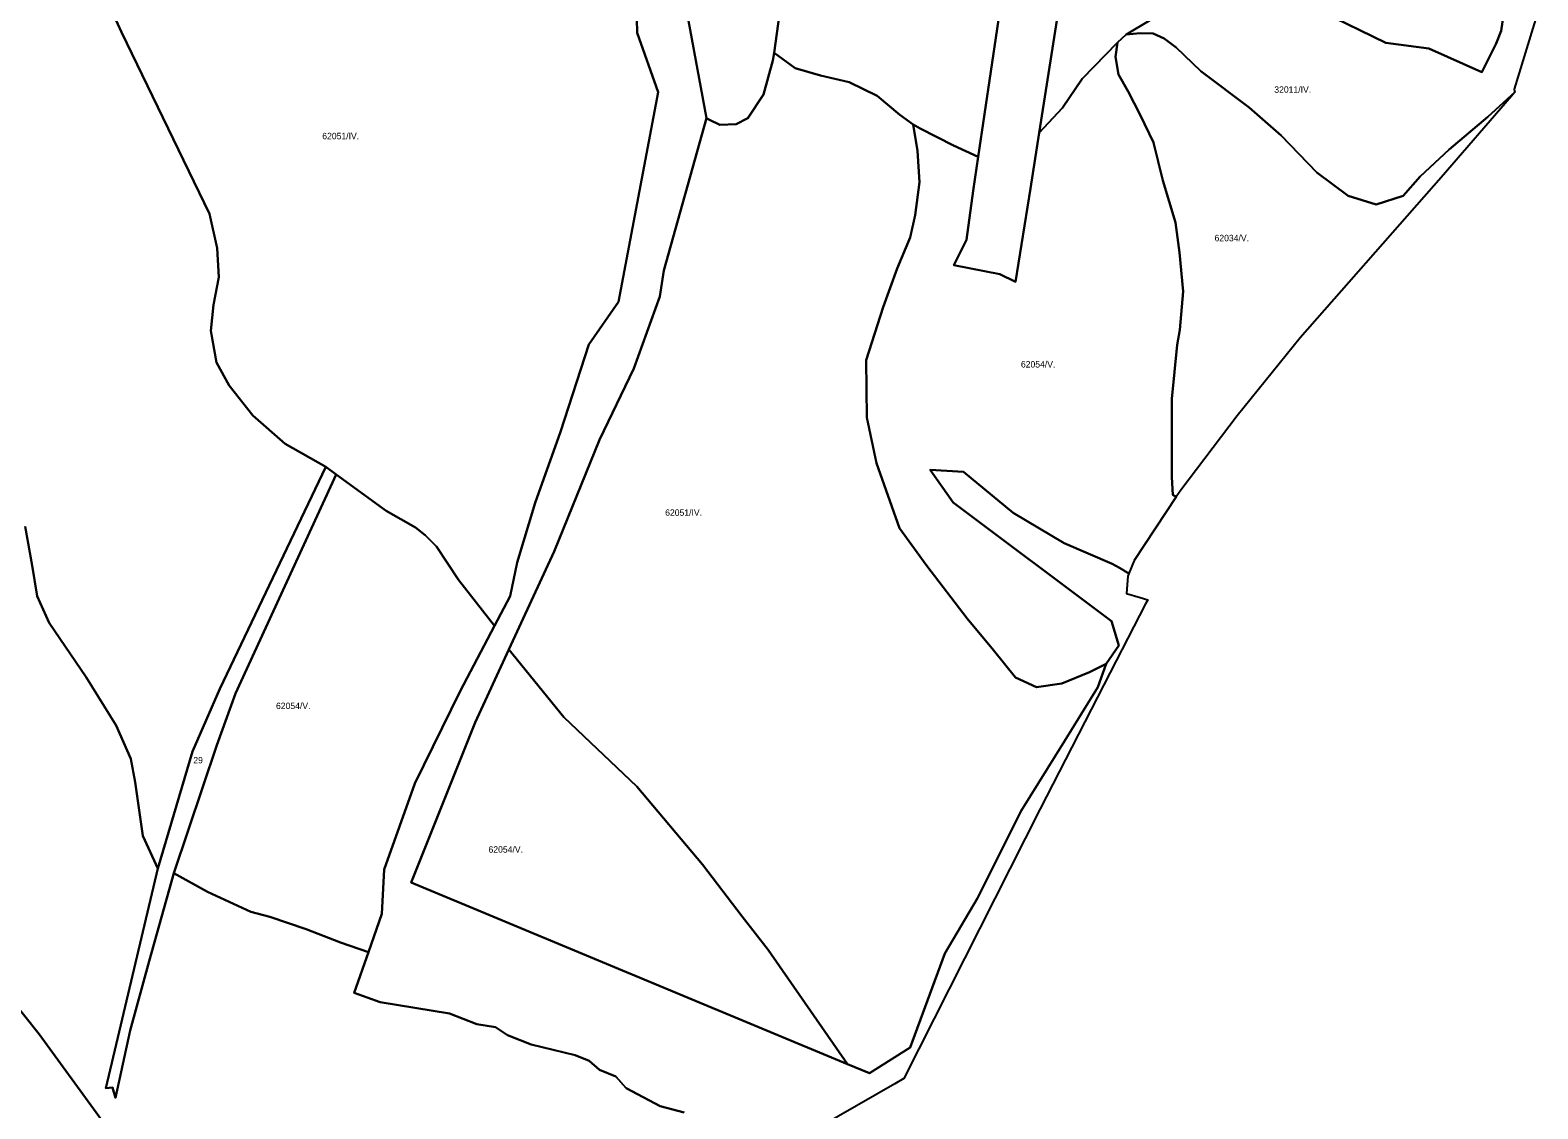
# Model space of a CAD drawing. Extents: x -521621 to -516761, y -1190184 to -1184927.
# Drawn here: x -518423 to -517486, y -1188763 to -1188092 of the extents above; entities that cross this region are included whole.
import ezdxf

# ---------------------------------------------------------------- set-up
doc = ezdxf.new("R2010")
doc.units = 0
doc.layers.add('BPEJ_s', color=7, linetype='Continuous')

msp = doc.modelspace()

# ---------------------------------------------------------------- linework, layer by layer
at = {"layer": 'BPEJ_s'}
for points in [[(-518018.47, -1188061.62), (-518012.46, -1188036.29), (-518000.06, -1188017), (-517983.54, -1188011.03), (-517972.06, -1188014.7), (-517961.5, -1188041.34), (-517957.37, -1188082.23), (-517960.81, -1188106.35), (-517961.5, -1188111.16), (-517967.47, -1188132.29), (-517977.11, -1188146.99), (-517984.45, -1188150.67), (-517994.55, -1188151.13), (-518000.98, -1188147.91), (-518002.81, -1188146.9)], [(-517795.95, -1188155.97), (-517778.93, -1188047.85), (-517760.33, -1188054.17), (-517726.82, -1188062.71), (-517690.18, -1188069.86), (-517726.97, -1188086.09), (-517741.81, -1188094.89), (-517747.31, -1188099.84), (-517769.3, -1188122.39), (-517781.39, -1188140.55)], [(-517874.36, -1188150.84), (-517869.9, -1188153.42), (-517849.15, -1188163.89), (-517833.89, -1188171.06), (-517837.01, -1188192.21), (-517841.13, -1188222.59), (-517849, -1188238.34), (-517820.52, -1188243.96), (-517810.78, -1188248.83), (-517801.42, -1188190.71), (-517795.95, -1188155.97), (-517781.39, -1188140.55), (-517769.3, -1188122.39), (-517747.31, -1188099.84), (-517748.63, -1188108.79), (-517746.75, -1188119.77), (-517740.74, -1188130.42), (-517733.2, -1188144.83), (-517724.96, -1188162.17), (-517719.13, -1188185.68), (-517711.24, -1188211.77), (-517708.67, -1188230.48), (-517706.44, -1188254.68), (-517708.5, -1188278.71), (-517710.21, -1188287.98), (-517713.53, -1188321.61), (-517713.53, -1188370.25), (-517712.98, -1188381.18), (-517710.77, -1188382.58), (-517736.9, -1188422.17), (-517740.28, -1188430.26), (-517746.03, -1188426.56), (-517750.63, -1188424.26), (-517780.51, -1188411.31), (-517812.07, -1188392.51), (-517843.13, -1188366.94), (-517863.67, -1188365.69), (-517849.4, -1188385.99), (-517750.96, -1188459.75), (-517746.36, -1188474.86), (-517754.24, -1188486.36), (-517764.66, -1188491.5), (-517781.81, -1188498.69), (-517797.65, -1188500.87), (-517810.75, -1188494.86), (-517824.41, -1188477.92), (-517840.8, -1188458.24), (-517865.92, -1188425.45), (-517882.85, -1188401.95), (-517897.05, -1188361.51), (-517903.06, -1188333.09), (-517903.61, -1188297.56), (-517892.89, -1188264.55), (-517884.31, -1188240.52), (-517876.25, -1188221.21), (-517872.99, -1188207.31), (-517870.42, -1188186.71), (-517871.62, -1188167.32)], [(-517747.31, -1188099.84), (-517741.81, -1188094.89), (-517733.2, -1188094.03), (-517725.13, -1188094.37), (-517718.27, -1188097.46), (-517710.73, -1188102.95), (-517695.5, -1188117.75), (-517665.34, -1188140.3), (-517645.54, -1188157.68), (-517623.3, -1188180.84), (-517603.8, -1188195.17), (-517586.44, -1188200.66), (-517569.68, -1188195.17), (-517559.02, -1188183.28), (-517541.05, -1188166.52), (-517516.98, -1188146.09), (-517500.18, -1188130.78), (-517502.32, -1188133.26), (-517546.04, -1188183.88), (-517633.77, -1188283.59), (-517672.91, -1188332.15), (-517707.95, -1188378.31), (-517710.77, -1188382.58), (-517712.98, -1188381.18), (-517713.53, -1188370.25), (-517713.53, -1188321.61), (-517710.21, -1188287.98), (-517708.5, -1188278.71), (-517706.44, -1188254.68), (-517708.67, -1188230.48), (-517711.24, -1188211.77), (-517719.13, -1188185.68), (-517724.96, -1188162.17), (-517733.2, -1188144.83), (-517740.74, -1188130.42), (-517746.75, -1188119.77), (-517748.63, -1188108.79)], [(-518125.71, -1188477.5), (-518097.54, -1188416.46), (-518069.33, -1188346.96), (-518047.98, -1188302.74), (-518031.82, -1188257.89), (-518029.25, -1188241.72), (-518002.81, -1188146.9), (-518000.98, -1188147.91), (-517994.55, -1188151.13), (-517984.45, -1188150.67), (-517977.11, -1188146.99), (-517967.47, -1188132.29), (-517961.5, -1188111.16), (-517960.81, -1188106.35), (-517947.78, -1188115.91), (-517932, -1188120.38), (-517914.16, -1188124.5), (-517896.66, -1188133.08), (-517882.6, -1188144.83), (-517874.36, -1188150.84), (-517871.62, -1188167.32), (-517870.42, -1188186.71), (-517872.99, -1188207.31), (-517876.25, -1188221.21), (-517884.31, -1188240.52), (-517892.89, -1188264.55), (-517903.61, -1188297.56), (-517903.06, -1188333.09), (-517897.05, -1188361.51), (-517882.85, -1188401.95), (-517865.92, -1188425.45), (-517840.8, -1188458.24), (-517824.41, -1188477.92), (-517810.75, -1188494.86), (-517797.65, -1188500.87), (-517781.81, -1188498.69), (-517764.66, -1188491.5), (-517754.24, -1188486.36), (-517759.49, -1188500.82), (-517780.31, -1188534.51), (-517807.25, -1188577.81), (-517834.23, -1188632.22), (-517854.63, -1188666.47), (-517876.24, -1188725.09), (-517901.39, -1188741.05), (-517915.06, -1188735.35), (-517964.57, -1188664.16), (-517980.62, -1188643.52), (-518005.2, -1188611.28), (-518046.17, -1188562.63), (-518091.5, -1188519.46)], [(-518343.86, -1188613.76), (-518322.42, -1188540.85), (-518305.48, -1188501.87), (-518239.47, -1188363.9), (-518232.96, -1188368.68), (-518295.67, -1188504.74), (-518307.32, -1188537.05), (-518334.08, -1188616.67), (-518349.4, -1188671.33), (-518361.05, -1188714.49), (-518370.23, -1188756.36), (-518372.07, -1188749.81), (-518376.36, -1188750.22)], [(-518334.08, -1188616.67), (-518307.32, -1188537.05), (-518295.67, -1188504.74), (-518232.96, -1188368.68), (-518201.93, -1188391.27), (-518183.77, -1188401.59), (-518177.8, -1188406.32), (-518170.7, -1188413.43), (-518157.05, -1188434.2), (-518134.69, -1188462.81), (-518156.06, -1188503.26), (-518184.05, -1188560.89), (-518203.24, -1188614.38), (-518204.57, -1188641.82), (-518213.01, -1188665.81), (-518230.4, -1188659.71), (-518251.66, -1188651.44), (-518274.27, -1188643.73), (-518286.17, -1188640.56), (-518313.13, -1188628.26)], [(-518125.71, -1188477.5), (-518091.5, -1188519.46), (-518046.17, -1188562.63), (-518005.2, -1188611.28), (-517980.62, -1188643.52), (-517964.57, -1188664.16), (-517915.06, -1188735.35), (-518186.51, -1188622.32), (-518146.66, -1188522.9)]]:
    msp.add_lwpolyline(points, close=True, dxfattribs=at)
for points in [[(-517814.29, -1188038.1), (-517833.89, -1188171.06), (-517849.15, -1188163.89), (-517869.9, -1188153.42), (-517874.36, -1188150.84), (-517882.6, -1188144.83), (-517896.66, -1188133.08), (-517914.16, -1188124.5), (-517932, -1188120.38), (-517947.78, -1188115.91), (-517960.81, -1188106.35), (-517957.37, -1188082.23)], [(-517778.93, -1188047.85), (-517795.95, -1188155.97), (-517801.42, -1188190.71), (-517810.78, -1188248.83), (-517820.52, -1188243.96), (-517849, -1188238.34), (-517841.13, -1188222.59), (-517837.01, -1188192.21), (-517833.89, -1188171.06), (-517814.29, -1188038.1)], [(-518018.47, -1188061.62), (-518002.81, -1188146.9), (-518029.25, -1188241.72), (-518031.82, -1188257.89), (-518047.98, -1188302.74), (-518069.33, -1188346.96), (-518097.54, -1188416.46), (-518125.71, -1188477.5), (-518146.66, -1188522.9), (-518186.51, -1188622.32), (-517915.06, -1188735.35), (-517901.39, -1188741.05), (-517876.24, -1188725.09), (-517854.63, -1188666.47), (-517834.23, -1188632.22), (-517807.25, -1188577.81), (-517780.31, -1188534.51), (-517759.49, -1188500.82), (-517754.24, -1188486.36), (-517746.36, -1188474.86), (-517750.96, -1188459.75), (-517849.4, -1188385.99), (-517863.67, -1188365.69), (-517843.13, -1188366.94), (-517812.07, -1188392.51), (-517780.51, -1188411.31), (-517750.63, -1188424.26), (-517746.03, -1188426.56), (-517740.28, -1188430.26), (-517740.95, -1188431.88), (-517741.76, -1188442.57), (-517733.24, -1188445.16), (-517728.49, -1188446.61), (-517729.78, -1188449.05), (-517751.75, -1188491.77), (-517795.37, -1188576.57), (-517880.09, -1188744.37), (-517885.74, -1188747.6), (-517931.92, -1188774.05)], [(-518373.32, -1188078.61), (-518366.54, -1188093.37), (-518311.79, -1188206.42), (-518306.97, -1188227.73), (-518305.98, -1188245.9), (-518309.42, -1188263.09), (-518310.89, -1188279.3), (-518307.46, -1188298.95), (-518299.6, -1188313.19), (-518284.88, -1188331.85), (-518264.76, -1188349.53), (-518239.47, -1188363.9), (-518305.48, -1188501.87), (-518322.42, -1188540.85), (-518343.86, -1188613.76), (-518353.17, -1188593.35), (-518357.93, -1188560.02), (-518360.71, -1188545.35), (-518369.82, -1188524.72), (-518388.46, -1188494.57), (-518411.45, -1188460.84), (-518418.99, -1188444.18), (-518422.16, -1188425.14), (-518426.52, -1188400.94)], [(-518046.19, -1188085.08), (-518045.9, -1188093.97), (-518032.92, -1188130.72), (-518057.52, -1188261.2), (-518075.89, -1188287.67), (-518093.51, -1188342.06), (-518109.31, -1188386.17), (-518120.54, -1188423.41), (-518124.88, -1188444.26), (-518134.69, -1188462.81), (-518157.05, -1188434.2), (-518170.7, -1188413.43), (-518177.8, -1188406.32), (-518183.77, -1188401.59), (-518201.93, -1188391.27), (-518232.96, -1188368.68), (-518239.47, -1188363.9), (-518264.76, -1188349.53), (-518284.88, -1188331.85), (-518299.6, -1188313.19), (-518307.46, -1188298.95), (-518310.89, -1188279.3), (-518309.42, -1188263.09), (-518305.98, -1188245.9), (-518306.97, -1188227.73), (-518311.79, -1188206.42), (-518366.54, -1188093.37), (-518373.32, -1188078.61)], [(-517485.94, -1188080.73), (-517500.67, -1188128.84), (-517500.18, -1188130.78), (-517516.98, -1188146.09), (-517541.05, -1188166.52), (-517559.02, -1188183.28), (-517569.68, -1188195.17), (-517586.44, -1188200.66), (-517603.8, -1188195.17), (-517623.3, -1188180.84), (-517645.54, -1188157.68), (-517665.34, -1188140.3), (-517695.5, -1188117.75), (-517710.73, -1188102.95), (-517718.27, -1188097.46), (-517725.13, -1188094.37), (-517733.2, -1188094.03), (-517741.81, -1188094.89), (-517726.97, -1188086.09)], [(-517620.48, -1188080.59), (-517580.51, -1188100.15), (-517553.66, -1188103.58), (-517520.82, -1188118.44), (-517511.96, -1188100.43), (-517508.82, -1188092.71), (-517506.25, -1188075.85)], [(-517506.25, -1188075.85), (-517508.82, -1188092.71), (-517511.96, -1188100.43), (-517520.82, -1188118.44), (-517553.66, -1188103.58), (-517580.51, -1188100.15), (-517620.48, -1188080.59)], [(-518016.61, -1188765.36), (-518031.53, -1188761.48), (-518052.79, -1188750.23), (-518059.13, -1188743.07), (-518069.35, -1188738.98), (-518075.76, -1188733.31), (-518084.55, -1188729.83), (-518111.73, -1188723.08), (-518126.45, -1188717.35), (-518134.02, -1188712.45), (-518145.67, -1188710.4), (-518162.63, -1188703.85), (-518205.71, -1188696.71), (-518221.86, -1188690.99), (-518213.01, -1188665.81), (-518204.57, -1188641.82), (-518203.24, -1188614.38), (-518184.05, -1188560.89), (-518156.06, -1188503.26), (-518134.69, -1188462.81), (-518124.88, -1188444.26), (-518120.54, -1188423.41), (-518109.31, -1188386.17), (-518093.51, -1188342.06), (-518075.89, -1188287.67), (-518057.52, -1188261.2), (-518032.92, -1188130.72), (-518045.9, -1188093.97), (-518046.19, -1188085.08)], [(-518426.52, -1188400.94), (-518422.16, -1188425.14), (-518418.99, -1188444.18), (-518411.45, -1188460.84), (-518388.46, -1188494.57), (-518369.82, -1188524.72), (-518360.71, -1188545.35), (-518357.93, -1188560.02), (-518353.17, -1188593.35), (-518343.86, -1188613.76), (-518376.36, -1188750.22), (-518372.07, -1188749.81), (-518370.23, -1188756.36), (-518361.05, -1188714.49), (-518349.4, -1188671.33), (-518334.08, -1188616.67), (-518313.13, -1188628.26), (-518286.17, -1188640.56), (-518274.27, -1188643.73), (-518251.66, -1188651.44), (-518230.4, -1188659.71), (-518213.01, -1188665.81), (-518221.86, -1188690.99), (-518205.71, -1188696.71), (-518162.63, -1188703.85), (-518145.67, -1188710.4), (-518134.02, -1188712.45), (-518126.45, -1188717.35), (-518111.73, -1188723.08), (-518084.55, -1188729.83), (-518075.76, -1188733.31), (-518069.35, -1188738.98), (-518059.13, -1188743.07), (-518052.79, -1188750.23), (-518031.53, -1188761.48), (-518016.61, -1188765.36)], [(-518480.44, -1188633.02), (-518467.36, -1188644.92), (-518453.88, -1188663.57), (-518442.78, -1188683.01), (-518435.53, -1188694.4), (-518417.8, -1188716.79), (-518378.87, -1188769.99)], [(-518378.87, -1188769.99), (-518417.8, -1188716.79), (-518435.53, -1188694.4)]]:
    msp.add_lwpolyline(points, dxfattribs=at)

# ---------------------------------------------------------------- texts
for s, p in [('32011/IV.', (-517649.79, -1188131.17)), ('62051/IV.', (-518241.7, -1188160.07)), ('62034/V.', (-517686.94, -1188223.51)), ('62054/V.', (-517807.33, -1188302.05)), ('62051/IV.', (-518028.51, -1188394.29)), ('62054/V.', (-518270.46, -1188514.49)), ('29', (-518321.89, -1188548.27)), ('62054/V.', (-518138.34, -1188603.82))]:
    msp.add_text(s, height=4, dxfattribs=at).set_placement(p)

doc.saveas('drawing.dxf')
